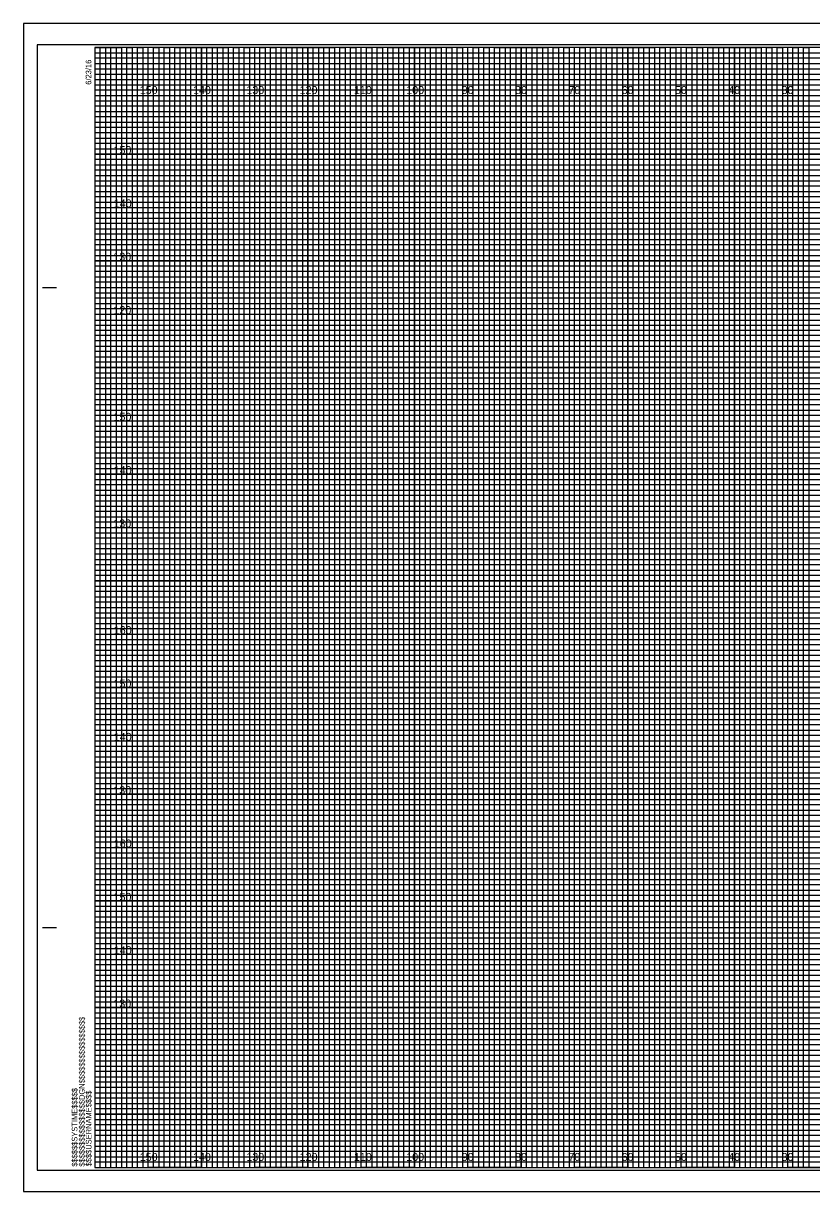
# Model space of a CAD drawing. Extents: x -13 to 323, y -5 to 434.
# Drawn here: x -13.4 to 134.5, y -4.5 to 214.5 of the extents above; entities that cross this region are included whole.
import ezdxf

# ---------------------------------------------------------------- set-up
doc = ezdxf.new("R2010")
doc.units = 0
for name, color, linetype in [('Exist Cross Section Cell', 7, 'Continuous'), ('Exist XS Center Line Elevation Label', 7, 'Continuous'), ('Exist XS Ground Line', 7, 'Continuous'), ('Prop CMT Pvmt Course 1', 7, 'Continuous'), ('Prop CMT Pvmt Course 3', 7, 'Continuous'), ('Prop CMT Pvmt Surface', 7, 'Continuous'), ('Prop CMT Pvmt Surface Shoulder', 7, 'Continuous'), ('Prop CMT Shld Paved Course 1', 7, 'Continuous'), ('Prop CMT Shld Paved Course 2', 7, 'Continuous'), ('Prop CMT Shld Paved Course 3', 7, 'Continuous'), ('Prop CMT Subgrade Earthwork', 7, 'Continuous')]:
    doc.layers.add(name, color=color, linetype=linetype)

msp = doc.modelspace()

# ---------------------------------------------------------------- linework, layer by layer
at = {"layer": 'Exist XS Center Line Elevation Label'}
for points in [[(0, 210), (5, 210), (5, 0), (15, 0), (15, 210), (25, 210), (25, 0), (35, 0), (35, 210), (45, 210), (45, 0), (55, 0), (55, 210), (65, 210), (65, 0), (75, 0), (75, 210), (85, 210), (85, 0), (95, 0), (95, 210), (105, 210), (105, 0), (115, 0), (115, 210), (125, 210), (125, 0), (135, 0)], [(0, 205), (275, 205)], [(0, 185), (320, 185), (320, 195), (0, 195)], [(0, 165), (320, 165), (320, 175), (0, 175)], [(0, 145), (320, 145), (320, 155), (0, 155)], [(0, 125), (320, 125), (320, 135), (0, 135)], [(0, 105), (320, 105), (320, 115), (0, 115)], [(0, 85), (320, 85), (320, 95), (0, 95)], [(0, 65), (320, 65), (320, 75), (0, 75)], [(0, 45), (320, 45), (320, 55), (0, 55)], [(0, 25), (320, 25), (320, 35), (0, 35)], [(0, 5), (320, 5), (320, 15), (0, 15)]]:
    msp.add_lwpolyline(points, dxfattribs=at)
at = {"layer": 'Exist XS Ground Line'}
for p, q in [((10, 210), (0, 210)), ((10, 0), (10, 210)), ((30, 210), (20, 210)), ((20, 210), (20, 0)), ((30, 0), (30, 210)), ((50, 210), (40, 210)), ((40, 210), (40, 0)), ((50, 0), (50, 210)), ((70, 210), (60, 210)), ((60, 210), (60, 0)), ((70, 0), (70, 210)), ((90, 210), (80, 210)), ((80, 210), (80, 0)), ((90, 0), (90, 210)), ((110, 210), (100, 210)), ((100, 210), (100, 0)), ((110, 0), (110, 210)), ((130, 210), (120, 210)), ((120, 210), (120, 0)), ((130, 0), (130, 210)), ((20, 0), (10, 0)), ((40, 0), (30, 0)), ((60, 0), (50, 0)), ((80, 0), (70, 0)), ((100, 0), (90, 0)), ((120, 0), (110, 0)), ((140, 0), (130, 0))]:
    msp.add_line(p, q, dxfattribs=at)
for points in [[(0, 200), (320, 200), (320, 190), (0, 190)], [(0, 180), (320, 180), (320, 170), (0, 170)], [(0, 160), (320, 160), (320, 150), (0, 150)], [(0, 140), (320, 140), (320, 130), (0, 130)], [(0, 120), (320, 120), (320, 110), (0, 110)], [(0, 100), (320, 100), (320, 90), (0, 90)], [(0, 80), (320, 80), (320, 70), (0, 70)], [(0, 60), (320, 60), (320, 50), (0, 50)], [(0, 40), (320, 40), (320, 30), (0, 30)], [(0, 20), (320, 20), (320, 10), (0, 10)]]:
    msp.add_lwpolyline(points, dxfattribs=at)
at = {"layer": 'Prop CMT Pvmt Course 3'}
msp.add_lwpolyline([(-13.4, -4.5), (323.3, -4.5), (323.3, 214.5), (-13.4, 214.5)], close=True, dxfattribs=at)
at = {"layer": 'Prop CMT Pvmt Surface'}
for p, q in [((10, 0), (10, 210)), ((20, 0), (20, 210)), ((30, 0), (30, 210)), ((40, 0), (40, 210)), ((50, 0), (50, 210)), ((60, 0), (60, 210)), ((70, 0), (70, 210)), ((80, 0), (80, 210)), ((90, 0), (90, 210)), ((100, 0), (100, 210)), ((110, 0), (110, 210)), ((120, 0), (120, 210)), ((130, 0), (130, 210)), ((0, 200), (320, 200)), ((0, 190), (320, 190)), ((0, 180), (320, 180)), ((0, 170), (320, 170)), ((0, 160), (320, 160)), ((0, 150), (320, 150)), ((0, 140), (320, 140)), ((0, 130), (320, 130)), ((0, 120), (320, 120)), ((0, 110), (320, 110)), ((0, 100), (320, 100)), ((0, 90), (320, 90)), ((0, 80), (320, 80)), ((0, 70), (320, 70)), ((0, 60), (320, 60)), ((0, 50), (320, 50)), ((0, 40), (320, 40)), ((0, 30), (320, 30)), ((0, 20), (320, 20)), ((0, 10), (320, 10))]:
    msp.add_line(p, q, dxfattribs=at)
at = {"layer": 'Prop CMT Pvmt Surface Shoulder'}
for p, q in [((323.3, 214.5), (-13.4, 214.5)), ((-13.4, 214.5), (-13.4, -4.5)), ((-13.4, -4.5), (323.3, -4.5))]:
    msp.add_line(p, q, dxfattribs=at)
at = {"layer": 'Prop CMT Shld Paved Course 1'}
for p, q in [((0, 209), (260, 209)), ((260, 207.98), (0, 207.98)), ((0, 207.98), (0, 207)), ((0, 207), (260, 207)), ((260, 205.89), (0, 205.89)), ((0, 205.89), (0, 204)), ((0, 204), (320, 204))]:
    msp.add_line(p, q, dxfattribs=at)
for points in [[(0, 203), (270, 203), (320, 203), (320, 202), (0, 202)], [(0, 201), (320, 201), (320, 199), (0, 199)], [(0, 198), (320, 198), (320, 197), (0, 196.98)], [(0, 196), (320, 196), (320, 194), (0, 194)], [(0, 193), (320, 193), (320, 192), (0, 192)], [(0, 191), (320, 191), (320, 189), (0, 189)], [(0, 188), (320, 188), (320, 187), (0, 187)], [(0, 186), (320, 186), (320, 184), (0, 184)], [(0, 183), (320, 183), (320, 182), (0, 182)], [(0, 181), (320, 181), (320, 179), (0, 179)], [(0, 178), (320, 178), (320, 177), (0, 177)], [(0, 176), (320, 176), (320, 173.95), (320, 173), (320, 172), (0, 172)], [(0, 174), (320, 174), (320, 173), (0, 173)], [(0, 171), (320, 171), (320, 169), (0, 169.03)], [(0, 169.03), (320, 169), (320, 168), (0, 168)], [(0, 167), (320, 167), (320, 166), (0, 166)], [(0, 164), (320, 164), (320, 163), (0, 163)], [(0, 162), (320, 162), (320, 161), (0, 161)], [(-0.07, 158.89), (320, 158.89), (320, 157.88), (-0.07, 157.88)], [(0, 157), (320, 157), (320, 156), (0, 156)], [(0, 154), (320, 154), (320, 153), (0, 153)], [(0, 152), (320, 152), (320, 151), (0, 151)], [(0, 149), (320, 149), (320, 148), (0, 148)], [(0, 147), (320, 147), (320, 146), (0, 146)], [(0, 144), (320, 144), (320, 143), (0, 143)], [(0, 142), (320, 142), (320, 141), (0, 141)], [(0, 139), (320, 139), (319.99, 137.98), (0, 138)], [(0, 137), (320, 137), (320, 136), (0, 136)], [(0, 134), (320, 134), (320, 133), (0, 133)], [(0, 132), (320, 132), (320, 131), (0, 131)], [(0, 129), (320, 129), (320, 128), (0, 128)], [(0, 127), (320, 127), (320, 126), (0, 126)], [(0, 124), (320, 124), (320, 123), (0, 123)], [(0, 122), (320, 122), (320, 121), (0, 121)], [(0, 119), (320, 119), (320, 118), (0, 118)], [(0, 116.99), (320.07, 116.91), (320, 116), (0, 116)], [(0, 114), (320, 114), (320, 113), (0, 113)], [(0, 112), (320, 112), (320, 111), (0, 111)], [(0, 109), (320, 109), (320, 108), (0, 108)], [(0, 107), (320, 107), (320, 106), (0, 106)], [(0, 104), (320, 104), (320, 103), (0, 103)], [(0, 102), (320, 102), (320, 101), (0, 101)], [(0, 99), (320, 99), (320, 98), (0, 98)], [(0, 97), (320, 97), (320, 96), (0, 96)], [(0, 94), (320, 94), (320, 93), (0, 93)], [(0, 92), (320, 92), (320, 91), (0, 91)], [(0, 89), (320, 89), (320, 88), (0, 88)], [(0, 87), (320, 87), (320, 86), (0, 86)], [(0, 84), (320, 84), (320, 83), (0, 83)], [(0, 82), (320, 82), (320, 81), (0, 81)], [(0, 79), (320, 79), (319.99, 77.98), (0, 78)], [(0, 77), (320, 77), (320, 76), (0, 76)], [(0, 74), (320, 74), (320, 73), (0, 73)], [(0, 72), (320, 72), (320, 71), (0, 71)], [(0, 69), (320, 69), (320, 68), (0, 68)], [(0, 67), (320, 67), (320, 66), (0, 66)], [(0, 64), (320, 64), (320, 63), (0, 63)], [(0, 62), (320, 62), (320, 61), (0, 61)], [(0, 59), (320, 59), (320, 58), (0, 58)], [(0, 56.99), (320.07, 56.91), (320, 56), (0, 56)], [(0, 54), (320, 54), (320, 53), (0, 53)], [(0, 52), (320, 52), (320, 51), (0, 51)], [(0, 49), (320, 49), (320, 48), (0, 48)], [(0, 47), (320, 47), (320, 46), (0, 46)], [(0, 44), (320, 44), (320, 43), (0, 43)], [(0, 42), (320, 42), (320, 41), (0, 41)], [(0, 39), (320, 39), (320, 38), (0, 38)], [(0, 37), (320, 37), (320, 36), (0, 36)], [(0, 34), (320, 34), (320, 33), (0, 33)], [(0, 32), (320, 32), (320, 31), (0, 31)], [(0, 29), (320, 29), (320, 28), (0, 28)], [(0, 27), (320, 27), (320, 26), (0, 26)], [(0, 24), (320, 24), (320, 23), (0, 23)], [(0, 22), (320, 22), (320, 21), (0, 21)], [(0, 19), (320, 19), (320, 18), (0, 18)], [(0, 17), (320, 17), (320, 16), (0, 16)], [(0, 14), (320, 14), (320, 13), (0, 13)], [(0, 12), (320, 12), (320, 11), (0, 11)], [(0, 9), (320, 9), (320, 8), (0, 8)], [(0, 7), (320, 7), (320, 6), (0, 6)], [(0, 4), (320, 4), (320, 3), (0, 3)], [(0, 2), (320, 2), (320, 1), (0, 1)]]:
    msp.add_lwpolyline(points, dxfattribs=at)
at = {"layer": 'Prop CMT Shld Paved Course 2'}
for p, q in [((-9.8, 165), (-7.3, 165)), ((-9.7, 165), (-7.2, 165)), ((-9.8, 45), (-7.3, 45)), ((-9.7, 45), (-7.2, 45)), ((0, 0), (0, 0)), ((0, 0), (0, 0)), ((0, 0), (0, 0)), ((0, 0), (0, 0)), ((0, 0), (0, 0)), ((0, 0), (0, 0)), ((0, 0), (0, 0))]:
    msp.add_line(p, q, dxfattribs=at)
msp.add_lwpolyline([(320, 210), (0, 210), (0, 0), (320, 0)], close=True, dxfattribs=at)
at = {"layer": 'Prop CMT Shld Paved Course 3'}
for points in [[(0, 0), (1, 0), (1, 210), (2, 210), (2, 0)], [(2, 0), (3, 0), (3, 210), (4, 210), (4, 0)], [(5, 0), (6, 0), (6, 210), (7, 210), (7, 0)], [(7, 0), (8, 0), (8, 210), (9, 210), (9, 0)], [(10, 0), (11, 0), (11, 210), (12, 210), (12, 0)], [(12, 0), (13, 0), (13, 210), (14, 210), (14, 0)], [(15, 0), (16, 0), (16, 210), (17, 210), (17, 0)], [(17, 0), (18, 0), (18, 210), (19, 210), (19, 0)], [(20, 0), (21, 0), (21, 210), (22, 210), (22, 0)], [(22, 0), (23, 0), (23, 210), (24, 210), (24, 0)], [(25, 0), (26, 0), (26, 210), (27, 210), (27, 0)], [(27, 0), (28, 0), (28, 210), (29, 210), (29, 0)], [(30, 0), (31, 0), (31, 210), (32, 210), (32, 0)], [(32, 0), (33, 0), (33, 210), (34, 210), (34, 0)], [(35, 0), (36, 0), (36, 210), (37, 210), (37, 0)], [(37, 0), (38, 0), (38, 210), (39, 210), (39, 0)], [(40, 0), (41, 0), (41, 210), (42, 210), (42, 0)], [(42, 0), (43, 0), (43, 210), (44, 210), (44, 0)], [(45, 0), (46, 0), (46, 210), (47, 210), (47, 0)], [(47, 0), (48, 0), (48, 210), (49, 210), (49, 0)], [(50, 0), (51, 0), (51, 210), (52, 210), (52, 0)], [(52, 0), (53, 0), (53, 210), (54, 210), (54, 0)], [(55, 0), (56, 0), (56, 210), (57, 210), (57, 0)], [(57, 0), (58, 0), (58, 210), (59, 210), (59, 0)], [(60, 0), (61, 0), (61, 210), (62, 210), (62, 0)], [(62, 0), (63, 0), (63, 210), (64, 210), (64, 0)], [(65, 0), (66, 0), (66, 210), (67, 210), (67, 0)], [(67, 0), (68, 0), (68, 210), (69, 210), (69, 0)], [(70, 0), (71, 0), (71, 210), (72, 210), (72, 0)], [(72, 0), (73, 0), (73, 210), (74, 210), (74, 0)], [(75, 0), (76, 0), (76, 210), (77, 210), (77, 0)], [(77, 0), (78, 0), (78, 210), (79, 210), (79, 0)], [(80, 0), (81, 0), (81, 210), (82, 210), (82, 0)], [(82, 0), (83, 0), (83, 210), (84, 210), (84, 0)], [(85, 0), (86, 0), (86, 210), (87, 210), (87, 0)], [(87, 0), (88, 0), (88, 210), (89, 210), (89, 0)], [(90, 0), (91, 0), (91, 210), (92, 210), (92, 0)], [(92, 0), (93, 0), (93, 210), (94, 210), (94, 0)], [(95, 0), (96, 0), (96, 210), (97, 210), (97, 0)], [(97, 0), (98, 0), (98, 210), (99, 210), (99, 0)], [(100, 0), (101, 0), (101, 210), (102, 210), (102, 0)], [(102, 0), (103, 0), (103, 210), (104, 210), (104, 0)], [(105, 0), (106, 0), (106, 210), (107, 210), (107, 0)], [(107, 0), (108, 0), (108, 210), (109, 210), (109, 0)], [(110, 0), (111, 0), (111, 210), (112, 210), (112, 0)], [(112, 0), (113, 0), (113, 210), (114, 210), (114, 0)], [(115, 0), (116, 0), (116, 210), (117, 210), (117, 0)], [(117, 0), (118, 0), (118, 210), (119, 210), (119, 0)], [(120, 0), (121, 0), (121, 210), (122, 210), (122, 0)], [(122, 0), (123, 0), (123, 210), (124, 210), (124, 0)], [(125, 0), (126, 0), (126, 210), (127, 210), (127, 0)], [(127, 0), (128, 0), (128, 210), (129, 210), (129, 0)], [(130, 0), (131, 0), (131, 210), (132, 210), (132, 0)], [(132, 0), (133, 0), (133, 210), (134, 210), (134, 0)]]:
    msp.add_lwpolyline(points, dxfattribs=at)
at = {"layer": 'Prop CMT Subgrade Earthwork'}
msp.add_lwpolyline([(-10.8, -0.5), (322.4, -0.5), (322.4, 210.5), (-10.8, 210.5)], close=True, dxfattribs=at)

# ---------------------------------------------------------------- texts
at = {"layer": 'Exist Cross Section Cell'}
for s, p in [('150', (8.44, 201.25)), ('140', (18.44, 201.25)), ('130', (28.44, 201.25)), ('120', (38.44, 201.25)), ('110', (48.62, 201.25)), ('100', (58.44, 201.25)), ('90', (68.86, 201.25)), ('80', (78.86, 201.25)), ('70', (88.86, 201.25)), ('60', (98.86, 201.25)), ('50', (108.86, 201.25)), ('40', (118.86, 201.25)), ('30', (128.86, 201.25)), ('150', (8.44, 1.25)), ('140', (18.44, 1.25)), ('130', (28.44, 1.25)), ('120', (38.44, 1.25)), ('110', (48.62, 1.25)), ('100', (58.44, 1.25)), ('90', (68.86, 1.25)), ('80', (78.86, 1.25)), ('70', (88.86, 1.25)), ('60', (98.86, 1.25)), ('50', (108.86, 1.25)), ('40', (118.86, 1.25)), ('30', (128.86, 1.25))]:
    msp.add_text(s, height=1.5, dxfattribs=at).set_placement(p)
at = {"layer": 'Prop CMT Pvmt Course 1'}
for s, p in [('150', (3.52, 190)), ('140', (3.57, 180)), ('130', (3.49, 170)), ('120', (3.5, 160)), ('150', (3.52, 140)), ('140', (3.57, 130)), ('130', (3.49, 120)), ('160', (3.57, 100)), ('150', (3.52, 90)), ('140', (3.57, 80)), ('130', (3.49, 70)), ('160', (3.57, 60)), ('150', (3.52, 50)), ('140', (3.57, 40)), ('130', (3.49, 30))]:
    msp.add_text(s, height=1.5, dxfattribs=at).set_placement(p)
at = {"layer": 'Prop CMT Shld Paved Course 2'}
for s, p in [('6/23/16', (-0.65, 203)), ('$$$$$$$$$$$$$$$$DGN$$$$$$$$$$$$$$$$', (-1.88, 0.18)), ('$$$$$$SYSTIME$$$$$', (-3.26, 0.18)), ('$$$$USERNAME$$$$', (-0.62, 0.23))]:
    msp.add_text(s, height=1.05, rotation=90, dxfattribs=at).set_placement(p)

doc.saveas('drawing.dxf')
